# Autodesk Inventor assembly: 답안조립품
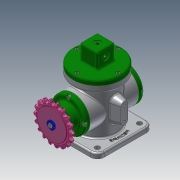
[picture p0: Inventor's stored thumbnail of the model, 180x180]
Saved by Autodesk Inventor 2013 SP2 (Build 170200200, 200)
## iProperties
Created: 2021-03
Part Number: 답안조립품
Document SubType Name: Assembly
Designer: kumcom8
Author: kumcom8
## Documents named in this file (19)
- C:\Users\kumcom8\Desktop\710306V1006\답안조립품.iam
- C:\Users\kumcom8\Desktop\710306V1006\본체.ipt
- C:\Users\kumcom8\Desktop\710306V1006\E-링.ipt
- C:\Users\kumcom8\Desktop\710306V1006\덮개.ipt
- C:\Users\kumcom8\Desktop\710306V1006\뒤커버.ipt
- C:\Users\kumcom8\Desktop\710306V1006\링크.ipt
- C:\Users\kumcom8\Desktop\710306V1006\멈춤나사 M3.ipt
- C:\Users\kumcom8\Desktop\710306V1006\베어링 17 x 40 x 12.ipt
- C:\Users\kumcom8\Desktop\710306V1006\볼트 M4 x 8.ipt
- C:\Users\kumcom8\Desktop\710306V1006\볼트 M4 x 10.ipt
- C:\Users\kumcom8\Desktop\710306V1006\스프로킷.ipt
- C:\Users\kumcom8\Desktop\710306V1006\슬라이더.ipt
- C:\Users\kumcom8\Desktop\710306V1006\앞커버.ipt
- C:\Users\kumcom8\Desktop\710306V1006\오일 실 17 30 8.ipt
- C:\Users\kumcom8\Desktop\710306V1006\와셔 4x16.ipt
- C:\Users\kumcom8\Desktop\710306V1006\클레비스 핀 6 x 22.ipt
- 클레비스 핀 6 x 22.ipt
- C:\Users\kumcom8\Desktop\710306V1006\키 4 x 4 x 12.ipt
- C:\Users\kumcom8\Desktop\710306V1006\편심축.ipt
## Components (1 placed, 1 different names)
1. E-링:1
